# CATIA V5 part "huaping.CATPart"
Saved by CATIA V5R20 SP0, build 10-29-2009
Part number: Part1
Material "Bottle Green": density 7860 kg/m3, Young's modulus 2e+11 Pa, Poisson ratio 0.266
Material "DS Light Blue": density 7860 kg/m3, Young's modulus 2e+11 Pa, Poisson ratio 0.266
Bounding box of the stored display mesh (mm): x -41.231 to 41.231, y -41.231 to 59.918, z 0 to 132.075
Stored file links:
  C:\Users\86155\Desktop\Part1.CATPart
  D:\catia  20\win_b64\startup\materials\Catalog.CATMaterial
  D:\catia  20\win_b64\startup\materials\blue_env_512x512.jpg
  D:\catia  20\win_b64\startup\materials\eroded_metal_1.jpg
  D:\catia  20\win_b64\startup\materials\eroded_metal_2.jpg
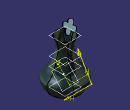
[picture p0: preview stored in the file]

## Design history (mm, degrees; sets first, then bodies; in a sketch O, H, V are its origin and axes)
Body1 (main body), material "Bottle Green"
  Plane1: type Offset, RefPlane xy-plane, Offset 20
  Plane2: type Offset, RefPlane Plane1, Offset 20
  Plane3: type Offset, RefPlane Plane2, Offset 20
  Plane4: type Offset, RefPlane Plane3, Offset 20
  Plane5: type Offset, RefPlane Plane4, Offset 20
  Sketch1 on xy-plane, origin (0, 0, 0), H (1, 0, 0), V (0, 1, 0)
    circle A1 centre (0, 0) radius 31.6228
  Sketch2 on Plane1, origin (0, 0, 20), H (1, 0, 0), V (0, 1, 0)
    circle A1 centre (0, 0) radius 41.2311
  Sketch3 on Plane2, origin (0, 0, 40), H (1, 0, 0), V (0, 1, 0)
    circle A1 centre (0, 0) radius 27
  Sketch4 on Plane3, origin (0, 0, 60), H (1, 0, 0), V (0, 1, 0)
    circle A1 centre (0, 0) radius 20
  Sketch5 on Plane4, origin (0, 0, 80), H (1, 0, 0), V (0, 1, 0)
    circle A1 centre (0, 0) radius 15
  Sketch6 on Plane5, origin (0, 0, 100), H (1, 0, 0), V (0, 1, 0)
    circle A1 centre (0, 0) radius 20
  Loft1: solid, Sections (Sketch1; Sketch2; Sketch3; Sketch4; Sketch5; Sketch6)
  Shell1: IntOffset 1, Face face of Loft1, ExtOffset 0
  Sketch7 on yz-plane, origin (0, 0, 0), H (0, 1, 0), V (0, 0, 1)
    point P1 (0, 40)
    line L1 (0, 40) -> (25, 40)
    point P2 (25, 40)
    line L2 (25, 40) -> (30, 30)
    line L3 (30, 30) -> (40, 20)
    line L4 (40, 20) -> (30, 0)
    point P5 (30, 0)
    line L5 (30, 0) -> (0, 0)
    line L6 (0, 0) -> (0, 40)
    axis line L7 (0, 110) -> (0, -10)
    point P6 (0, 110)
    distance P2 V = 25
    coincidence: P1 V, P5 H, P6 V
    horizontal: L1 H, L5 H
    vertical: L6 V, L7 V
  Shaft1: profile Sketch7, axis Sketch7.L7, angle 360
Body2, material "DS Light Blue"
  Sketch8 on yz-plane, origin (0, 0, 0), H (0, 1, 0), V (0, 0, 1)
    point P1 (0, 40)
    line L1 (0, 40) -> (25, 40)
    point P2 (25, 40)
    line L2 (25, 40) -> (30, 30)
    line L3 (30, 30) -> (40, 20)
    line L4 (40, 20) -> (30, 0)
    point P5 (30, 0)
    line L5 (30, 0) -> (0, 0)
    line L6 (0, 0) -> (0, 40)
    axis line L7 (0, 120) -> (0, -10)
    point P6 (0, 120)
    distance P2 V = 25
    coincidence: P1 V, P5 H, P6 V
    horizontal: L1 H, L5 H
    vertical: L6 V, L7 V
  Shaft2: profile Sketch8, axis Sketch8.L7, angle 360
  Sketch9 on yz-plane, origin (0, 0, 0), H (0, 1, 0), V (0, 0, 1)
    spline S1 through (0, 20) (10, 70) (0, 110) (10, 120)
    point P1 (0, 110)
    coincidence: P1 V
  Plane6: type Normal, Curve Sketch9, RefPoint vertex of Sketch9
  Sketch10 on Plane6, origin (0, 59.9184, 35.3228), H (-1, 0, 0), V (0, -0.5078, 0.8615)
    arc A1 centre (-5.8077, 105.8077) radius 5.9288 from (-7, 100) to (0, 107) cw
    point P3 (0, 107)
    arc A2 centre (5.8077, 105.8077) radius 5.9288 from (0, 107) to (7, 100) cw
    arc A3 centre (-5.8077, 94.1923) radius 5.9288 from (-7, 100) to (0, 93) ccw
    point P7 (0, 93)
    arc A4 centre (5.8077, 94.1923) radius 5.9288 from (7, 100) to (0, 93) cw
    coincidence: P3 V, P7 V
  Plane7: type Normal, Curve Sketch9, RefPoint vertex of Sketch9
  Plane8: type Normal, Curve Sketch9
  Plane9: type Normal, Curve Sketch9, RefPoint vertex of Sketch9
  Sketch11 on Plane9, origin (0, 9.9123, 8.6789), H (-1, 0, 0), V (0, -0.6587, 0.7524)
    circle A1 centre (0, 20) radius 1
    point P1 (0, 20)
    coincidence: P1 V
  Plane10: type Normal, Curve Sketch9, RefPoint vertex of Sketch9
  Circle1: type CtrRad, Start 0, End 180, Center vertex of Sketch9, Support Plane10, Radius 1, FirstDirection (-1, 0, 0)
  Rib1: profile Circle1, centre curve Sketch9
  Pad1: profile Sketch10, direction (0, 0.8615, 0.5078), length 1
  Sketch12 on start face of Pad1, origin (0, 59.9184, 35.3228), H (1, 0, 0), V (0, -0.5078, 0.8615)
